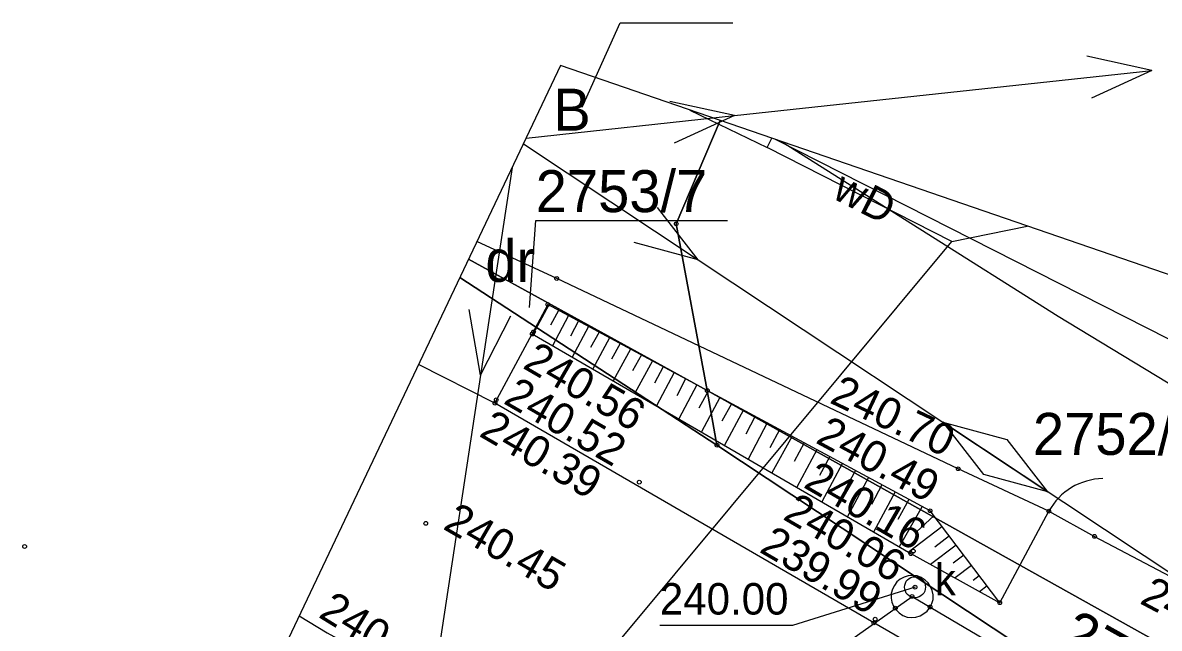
# Model space of a CAD drawing. Extents: x 6596400 to 6597200, y 5539751 to 5540251.
# Drawn here: x 6596646.54 to 6596673.62, y 5540120.52 to 5540134.94 of the extents above; entities that cross this region are included whole.
import ezdxf

# ---------------------------------------------------------------- set-up
doc = ezdxf.new("R2010")
doc.units = 0
for name, color, linetype in [('000 Inne (niezydentyfikowane)', 7, 'Continuous'), ('140-Punkty robocze', 7, 'Continuous'), ('203-punkt graniczny', 7, 'Continuous'), ('210-oznaczenie konturu użytku gruntowego', 7, 'Continuous'), ('211-numer działki ewidencyjnej', 7, 'Continuous'), ('218-kontur użytku gruntowego', 7, 'Continuous'), ('219-działka ewidencyjna', 7, 'Continuous'), ('brama', 7, 'Continuous'), ('chodnik', 7, 'Continuous'), ('furtka', 7, 'Continuous'), ('jezdnia', 7, 'Continuous'), ('komora podziemna', 7, 'Continuous'), ('krawężnik', 7, 'Continuous'), ('Linia obszaru zagospodarowania terenu', 7, 'Continuous'), ('ogrodzenie trwałe', 7, 'Continuous'), ('pikieta sztuczna', 7, 'Continuous'), ('pikieta sztuczna-Atr2', 7, 'Continuous'), ('przewód elektroenergetyczny niskiego napięcia', 7, 'Continuous'), ('przewód kanalizacyjny', 7, 'Continuous'), ('przewód telekomunikacyjny podziemny', 7, 'Continuous'), ('przewód wodociągowy', 7, 'Continuous'), ('przewód wodociągowy-Atr1', 7, 'Continuous'), ('rzedna', 7, 'Continuous'), ('rzedna-Atr2', 7, 'Continuous'), ('skarpa nieumocniona', 7, 'Continuous'), ('właz do komory lub kanału - okrągły', 7, 'Continuous'), ('właz do komory lub kanału - okrągły-Atr17', 7, 'Continuous'), ('Zakres', 7, 'Continuous')]:
    doc.layers.add(name, color=color, linetype=linetype)

# ---------------------------------------------------------------- blocks, each defined once
blk = doc.blocks.new('203')
blk.add_circle((0, 0), 0.045)
blk = doc.blocks.new('SUEP1')
for p, q in [((5, 0), (3.5, 0.5)), ((15, 0), (13.5, 0.5)), ((0, 0), (5, 0)), ((5, 0), (3.5, -0.5)), ((5, 0), (15, 0)), ((15, 0), (13.5, -0.5))]:
    blk.add_line(p, q)
blk = doc.blocks.new('OK04')
blk.add_arc((1.5, 0.001), 1.5, 120, 180)
blk = doc.blocks.new('US22')
blk.add_circle((0, 0), 0.25)
blk = doc.blocks.new('PW01')
blk.add_circle((0, 0), 0.045)
blk = doc.blocks.new('PIKIETA')
blk.add_circle((0, 0), 0.045)

msp = doc.modelspace()

# ---------------------------------------------------------------- linework, layer by layer
at = {"layer": '000 Inne (niezydentyfikowane)'}
for points in [[(6596659.07, 5540128.22), (6596658.69, 5540127.52)], [(6596659.3, 5540128.09), (6596659.11, 5540127.74)], [(6596659.54, 5540127.97), (6596659.16, 5540127.25)], [(6596659.78, 5540127.84), (6596659.59, 5540127.48)], [(6596660.02, 5540127.71), (6596659.63, 5540126.98)], [(6596660.27, 5540127.57), (6596660.07, 5540127.21)], [(6596660.52, 5540127.44), (6596660.12, 5540126.7)], [(6596660.77, 5540127.3), (6596660.57, 5540126.93)], [(6596661.02, 5540127.17), (6596660.61, 5540126.41)], [(6596661.28, 5540127.03), (6596661.07, 5540126.65)], [(6596661.54, 5540126.89), (6596661.12, 5540126.12)], [(6596661.8, 5540126.75), (6596661.59, 5540126.36)], [(6596662.06, 5540126.61), (6596661.64, 5540125.82)], [(6596662.33, 5540126.46), (6596662.12, 5540126.06)], [(6596662.6, 5540126.32), (6596662.17, 5540125.51)], [(6596662.87, 5540126.17), (6596662.65, 5540125.76)], [(6596663.15, 5540126.02), (6596662.71, 5540125.2)], [(6596663.43, 5540125.87), (6596663.2, 5540125.45)], [(6596663.71, 5540125.72), (6596663.26, 5540124.88)], [(6596663.99, 5540125.57), (6596663.77, 5540125.14)], [(6596664.28, 5540125.41), (6596663.82, 5540124.55)], [(6596664.57, 5540125.25), (6596664.34, 5540124.82)], [(6596664.87, 5540125.1), (6596664.39, 5540124.22)], [(6596665.16, 5540124.94), (6596664.92, 5540124.49)], [(6596665.46, 5540124.77), (6596664.98, 5540123.88)], [(6596665.77, 5540124.61), (6596665.52, 5540124.16)], [(6596666.07, 5540124.45), (6596665.58, 5540123.53)], [(6596666.38, 5540124.28), (6596666.13, 5540123.82)], [(6596666.69, 5540124.11), (6596666.19, 5540123.18)], [(6596667.01, 5540123.94), (6596666.76, 5540123.47)], [(6596667.33, 5540123.77), (6596666.81, 5540122.81)], [(6596667.65, 5540123.59), (6596667.39, 5540123.11)], [(6596667.97, 5540123.42), (6596667.42, 5540122.46)], [(6596668.25, 5540123.2), (6596667.84, 5540122.83)], [(6596668.44, 5540122.94), (6596667.64, 5540122.33)], [(6596668.62, 5540122.72), (6596668.27, 5540122.45)], [(6596668.78, 5540122.5), (6596668.17, 5540122.04)], [(6596668.96, 5540122.26), (6596668.71, 5540122.07)], [(6596669.15, 5540122.02), (6596668.76, 5540121.72)], [(6596669.33, 5540121.77), (6596669.19, 5540121.66)], [(6596669.52, 5540121.53), (6596669.34, 5540121.39)]]:
    msp.add_lwpolyline(points, dxfattribs=at)
at = {"layer": '211-numer działki ewidencyjnej'}
for points in [[(6596659.87, 5540132.93), (6596660.77, 5540134.94), (6596663.461, 5540134.94)], [(6596658.61, 5540128.16), (6596658.76, 5540130.23), (6596663.33, 5540130.23)]]:
    msp.add_lwpolyline(points, dxfattribs=at)
at = {"layer": '218-kontur użytku gruntowego'}
for points in [[(6596662.11, 5540130.15), (6596663.159, 5540132.612)], [(6596663.159, 5540132.612), (6596662.11, 5540130.15)], [(6596662.85, 5540126.18), (6596662.11, 5540130.15)], [(6596662.11, 5540130.15), (6596662.85, 5540126.18)], [(6596657.158, 5540129.307), (6596662.85, 5540126.18)], [(6596662.85, 5540126.18), (6596657.158, 5540129.307)], [(6596656.952, 5540128.874), (6596663.08, 5540124.88)], [(6596663.08, 5540124.88), (6596656.952, 5540128.874)], [(6596681.92, 5540115.54), (6596662.85, 5540126.18)], [(6596662.85, 5540126.18), (6596663.08, 5540124.88)], [(6596663.08, 5540124.88), (6596662.85, 5540126.18)], [(6596662.85, 5540126.18), (6596681.92, 5540115.54)], [(6596663.08, 5540124.88), (6596681.02, 5540113.01)], [(6596681.02, 5540113.01), (6596663.08, 5540124.88)]]:
    msp.add_lwpolyline(points, dxfattribs=at)
at = {"layer": '219-działka ewidencyjna'}
for points in [[(6596662.11, 5540130.15), (6596663.159, 5540132.612)], [(6596662.85, 5540126.18), (6596662.11, 5540130.15)], [(6596662.85, 5540126.18), (6596657.158, 5540129.307)], [(6596663.08, 5540124.88), (6596656.952, 5540128.874)], [(6596681.92, 5540115.54), (6596662.85, 5540126.18)], [(6596663.08, 5540124.88), (6596662.85, 5540126.18)], [(6596681.02, 5540113.01), (6596663.08, 5540124.88)]]:
    msp.add_lwpolyline(points, dxfattribs=at)
at = {"layer": 'brama'}
msp.add_lwpolyline([(6596672.08, 5540122.71), (6596677.31, 5540119.95)], dxfattribs=at)
at = {"layer": 'chodnik'}
msp.add_lwpolyline([(6596679.35, 5540113.39), (6596672.62, 5540117.3), (6596666.82, 5540120.65), (6596657.79, 5540125.88), (6596658.68, 5540127.53), (6596667.7, 5540122.3), (6596669.82, 5540121.13), (6596670.99, 5540123.31), (6596672.08, 5540122.71), (6596677.31, 5540119.95)], dxfattribs=at)
at = {"layer": 'furtka'}
msp.add_lwpolyline([(6596670.99, 5540123.31), (6596672.08, 5540122.71)], dxfattribs=at)
at = {"layer": 'jezdnia'}
for points in [[(6596728.26, 5540094.5), (6596723.35, 5540095.14), (6596720.92, 5540095.72), (6596718.03, 5540096.54), (6596712.8, 5540098.2), (6596708.8, 5540099.55), (6596704.7, 5540101.24), (6596694.34, 5540105.7), (6596683.34, 5540111.32), (6596679.35, 5540113.39), (6596672.62, 5540117.3), (6596666.82, 5540120.65), (6596657.79, 5540125.88), (6596655.967, 5540126.802)], [(6596653.124, 5540120.82), (6596653.79, 5540120.41), (6596660.56, 5540116.72), (6596663.8, 5540114.85), (6596668, 5540112.34), (6596669.54, 5540111.42), (6596675.97, 5540107.49), (6596679.93, 5540105.19), (6596682.35, 5540103.89), (6596691.43, 5540099.24), (6596702.2, 5540094.56), (6596706.34, 5540093.02), (6596710.59, 5540091.59), (6596715.92, 5540090.16), (6596720.02, 5540089.23), (6596724.29, 5540088.47), (6596726.93, 5540087.96), (6596734.57, 5540086.51), (6596738.41, 5540085.75), (6596741.83, 5540085.11), (6596743.38, 5540084.84), (6596743.64, 5540085.7), (6596748.72, 5540084.9)]]:
    msp.add_lwpolyline(points, dxfattribs=at)
at = {"layer": 'komora podziemna'}
msp.add_lwpolyline([(6596667.35, 5540120.96), (6596667.42, 5540120.89), (6596667.51, 5540120.83), (6596667.61, 5540120.79), (6596667.71, 5540120.78), (6596667.82, 5540120.79), (6596667.92, 5540120.82), (6596668.01, 5540120.87), (6596668.09, 5540120.93), (6596668.15, 5540121.02), (6596668.2, 5540121.11), (6596668.23, 5540121.21), (6596668.23, 5540121.32), (6596668.21, 5540121.42), (6596668.17, 5540121.51), (6596668.11, 5540121.6), (6596668.04, 5540121.67), (6596667.95, 5540121.73), (6596667.85, 5540121.77), (6596667.75, 5540121.78), (6596667.64, 5540121.77), (6596667.54, 5540121.74), (6596667.45, 5540121.69), (6596667.37, 5540121.63), (6596667.31, 5540121.54), (6596667.26, 5540121.45), (6596667.23, 5540121.35), (6596667.23, 5540121.24), (6596667.25, 5540121.14), (6596667.29, 5540121.05)], close=True, dxfattribs=at)
at = {"layer": 'krawężnik'}
for points in [[(6596712.8, 5540098.2), (6596708.8, 5540099.55), (6596704.7, 5540101.24), (6596694.34, 5540105.7), (6596683.34, 5540111.32), (6596679.35, 5540113.39), (6596672.62, 5540117.3), (6596666.82, 5540120.65), (6596657.79, 5540125.88), (6596655.967, 5540126.802)], [(6596653.124, 5540120.82), (6596653.79, 5540120.41), (6596660.56, 5540116.72), (6596663.8, 5540114.85), (6596668, 5540112.34), (6596669.54, 5540111.42), (6596675.97, 5540107.49), (6596679.93, 5540105.19), (6596682.35, 5540103.89), (6596691.43, 5540099.24), (6596702.2, 5540094.56), (6596706.34, 5540093.02), (6596710.59, 5540091.59)]]:
    msp.add_lwpolyline(points, dxfattribs=at)
at = {"layer": 'Linia obszaru zagospodarowania terenu'}
msp.add_lwpolyline([(6596664.616, 5540132.112), (6596671.21, 5540127.95), (6596681.8, 5540121.54), (6596690.35, 5540115.69), (6596701.61, 5540105.97), (6596709.34, 5540098.61), (6596715.39, 5540091.82), (6596718.63, 5540088.53), (6596721.87, 5540084.71), (6596726.1, 5540083.21), (6596730.7, 5540082.79), (6596730.91, 5540075), (6596745.51, 5540074.64), (6596746.77, 5540082.74), (6596765.15, 5540085.09), (6596776.62, 5540086.27), (6596789.34, 5540086.1), (6596798.37, 5540085.54), (6596805.65, 5540083.56), (6596813.11, 5540081.53), (6596819.41, 5540077.54), (6596826.58, 5540072.81), (6596832.721, 5540067.998)], dxfattribs=at)
at = {"layer": 'ogrodzenie trwałe'}
msp.add_lwpolyline([(6596670.99, 5540123.31), (6596668.83, 5540124.32), (6596659.26, 5540128.85), (6596657.36, 5540129.733)], dxfattribs=at)
at = {"layer": 'przewód kanalizacyjny'}
msp.add_lwpolyline([(6596652.409, 5540119.314), (6596659.51, 5540115.47), (6596667.73, 5540121.28), (6596680.3, 5540113.87), (6596707.99, 5540100.58), (6596711.34, 5540100.47), (6596715.95, 5540100.45)], dxfattribs=at)
at = {"layer": 'przewód telekomunikacyjny podziemny'}
msp.add_lwpolyline([(6596689.623, 5540123.524), (6596689.22, 5540123.39), (6596674.88, 5540126.88), (6596664.474, 5540132.16)], dxfattribs=at)
at = {"layer": 'przewód wodociągowy'}
for points in [[(6596662.433, 5540132.861), (6596664.28, 5540131.97)], [(6596664.28, 5540131.97), (6596664.386, 5540132.191)], [(6596668.68, 5540129.73), (6596664.28, 5540131.97)], [(6596668.68, 5540129.73), (6596670.473, 5540130.1)], [(6596650.243, 5540107.602), (6596668.68, 5540129.73)]]:
    msp.add_lwpolyline(points, dxfattribs=at)
at = {"layer": 'rzedna-Atr2'}
msp.add_lwpolyline([(6596667.8, 5540121.5), (6596664.88, 5540120.59), (6596661.718, 5540120.59)], dxfattribs=at)
at = {"layer": 'skarpa nieumocniona'}
msp.add_lwpolyline([(6596669.82, 5540121.13), (6596668.16, 5540123.32), (6596659.05, 5540128.23), (6596658.68, 5540127.53), (6596667.7, 5540122.3)], close=True, dxfattribs=at)
msp.add_lwpolyline([(6596669.82, 5540121.13), (6596668.16, 5540123.32), (6596659.05, 5540128.23), (6596658.68, 5540127.53), (6596667.7, 5540122.3)], close=True, dxfattribs=at)
at = {"layer": 'Zakres'}
msp.add_lwpolyline([(6596822.22, 5540097.5), (6596800.39, 5540105.4), (6596755.76, 5540121.45), (6596697.73, 5540120.74), (6596659.35, 5540133.92), (6596647.64, 5540109.28), (6596697.73, 5540077), (6596721.01, 5540057.77), (6596727.72, 5540045.95), (6596731.95, 5540033.61), (6596741.17, 5540031.18), (6596755.59, 5540029.2), (6596757.85, 5540044.22), (6596787.25, 5540055.04), (6596806.3, 5540048.33), (6596813.97, 5540042.6), (6596833.15, 5540068.58), (6596822.3, 5540077.75)], close=True, dxfattribs=at)

# ---------------------------------------------------------------- block references
at = {"layer": '140-Punkty robocze'}
for p in [(6596659.26, 5540128.85), (6596659.05, 5540128.23), (6596658.71, 5540127.58), (6596661.23, 5540124), (6596670.99, 5540123.31), (6596672.08, 5540122.71), (6596646.58, 5540122.47), (6596667.8, 5540121.5), (6596667.73, 5540121.28), (6596669.82, 5540121.13), (6596667.33, 5540121), (6596668.16, 5540121.03)]:
    msp.add_blockref('PIKIETA', p, dxfattribs=at)
at = {"layer": '203-punkt graniczny'}
for p in [(6596662.11, 5540130.15), (6596662.85, 5540126.18), (6596663.08, 5540124.88)]:
    msp.add_blockref('203', p, dxfattribs=at)
at = {"layer": 'furtka', "rotation": -28.830999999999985}
msp.add_blockref('OK04', (6596670.99, 5540123.31), dxfattribs=at)
at = {"layer": 'pikieta sztuczna'}
for p in [(6596658.68, 5540127.53), (6596657.82, 5540125.96), (6596657.79, 5540125.88), (6596668.83, 5540124.32), (6596668.16, 5540123.32), (6596656.14, 5540123.02), (6596667.7, 5540122.3), (6596667.76, 5540122.36), (6596666.82, 5540120.65), (6596666.85, 5540120.74)]:
    msp.add_blockref('PW01', p, dxfattribs=at)
at = {"layer": 'przewód elektroenergetyczny niskiego napięcia'}
for p, rotation in [((6596658.53, 5540132.195), 6.163), ((6596658.466, 5540132.06), -33.55599999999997), ((6596658.197, 5540131.494), -98.649), ((6596680.96, 5540117.14), 146.444)]:
    msp.add_blockref('SUEP1', p, dxfattribs=dict(at, rotation=rotation))
at = {"layer": 'rzedna'}
msp.add_blockref('PW01', (6596667.8, 5540121.5), dxfattribs=at)
at = {"layer": 'właz do komory lub kanału - okrągły'}
msp.add_blockref('US22', (6596667.8, 5540121.5), dxfattribs=at)

# ---------------------------------------------------------------- texts
at = {"layer": '210-oznaczenie konturu użytku gruntowego'}
for s, p in [('B', (6596659.18, 5540132.37)), ('dr', (6596657.56, 5540128.77))]:
    msp.add_text(s, height=1, dxfattribs=at).set_placement(p)
at = {"layer": '211-numer działki ewidencyjnej'}
for s, p in [('2753/7', (6596658.76, 5540130.43)), ('2752/6', (6596670.61, 5540124.65))]:
    msp.add_text(s, height=1, dxfattribs=at).set_placement(p)
msp.add_text('2752/5', height=1, rotation=330.841, dxfattribs=at).set_placement((6596671.18, 5540120.13))
at = {"layer": 'pikieta sztuczna-Atr2'}
for s, rotation, p in [('240.56', 329.894, (6596658.424, 5540126.731)), ('240.70', 334.669, (6596665.739, 5540125.902)), ('240.52', 329.921, (6596657.964, 5540125.891)), ('240.39', 329.921, (6596657.384, 5540125.111)), ('240.49', 331.677, (6596665.404, 5540124.95)), ('240.16', 329.894, (6596665.114, 5540123.891)), ('240.06', 329.894, (6596664.624, 5540123.131)), ('240.45', 329.921, (6596656.524, 5540122.901)), ('239.99', 329.921, (6596664.064, 5540122.351)), ('240.01', 332.178, (6596673.13, 5540121.127)), ('240.44', 328.383, (6596653.557, 5540120.801))]:
    msp.add_text(s, height=0.75, rotation=rotation, dxfattribs=at).set_placement(p)
at = {"layer": 'przewód wodociągowy-Atr1'}
msp.add_text('wD', height=0.75, rotation=333.02, dxfattribs=at).set_placement((6596665.794, 5540130.778))
at = {"layer": 'rzedna-Atr2'}
msp.add_text('240.00', height=0.75, dxfattribs=at).set_placement((6596661.718, 5540120.848))
at = {"layer": 'właz do komory lub kanału - okrągły-Atr17'}
msp.add_text('k', height=0.75, dxfattribs=at).set_placement((6596668.27, 5540121.31))

doc.saveas('drawing.dxf')
